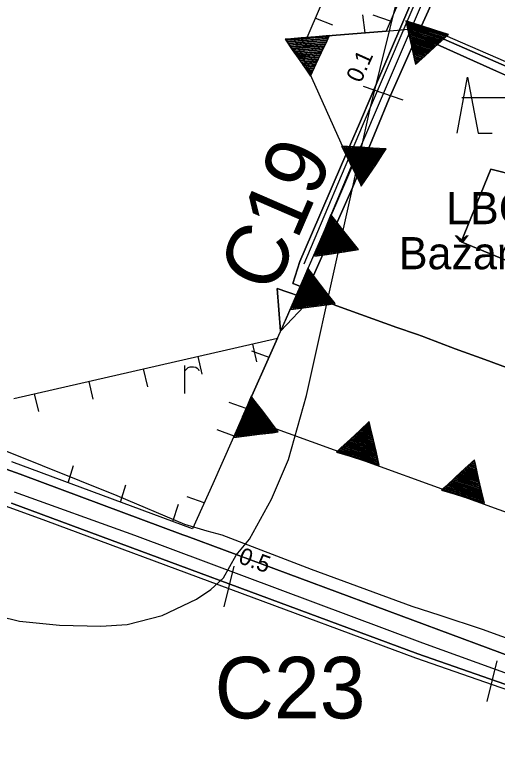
# Model space of a CAD drawing. Extents: x -645676 to -642474, y -1077513 to -1072613.
# Drawn here: x -643719.5 to -643546.9, y -1075297.8 to -1075036 of the extents above; entities that cross this region are included whole.
import ezdxf

# ---------------------------------------------------------------- set-up
doc = ezdxf.new("R2010")
doc.units = 0
for name, color, linetype in [('_elezni_n__tra_', 7, 'Continuous'), ('KULTURY_STAV', 7, 'Continuous'), ('KULTURY_ZNACKY', 7, 'Continuous'), ('Lok_ln__biocentrum___st_vaj_c_', 7, 'Continuous'), ('NERESENE_POZEMKY', 7, 'Continuous'), ('Obvod_KP_', 7, 'Continuous'), ('OBVOD_PU', 7, 'Continuous'), ('P__kop___st_vaj_c_', 7, 'Continuous'), ('PC_NAVRH', 7, 'Continuous'), ('PC_POPIS_NAVRH', 7, 'Continuous'), ('PC_POPIS_STAV', 7, 'Continuous'), ('PC_STAN_NAVRH', 7, 'Continuous'), ('PC_STAN_STAV', 7, 'Continuous'), ('PC_STAV', 7, 'Continuous'), ('SDELOVACI', 7, 'Continuous'), ('USES_BC_STAV', 7, 'Continuous'), ('USES_BK_NAVRH', 7, 'Continuous'), ('VRSTEVNICE', 7, 'Continuous')]:
    doc.layers.add(name, color=color, linetype=linetype)

# ---------------------------------------------------------------- blocks, each defined once
blk = doc.blocks.new('$943')
blk.add_line((0, 1.5), (0, -1.5))
blk = doc.blocks.new('$945')
for points in [[(0, 0), (-2.8, 1.25), (-2.8, -1.25), (0, 0)], [(-2.8, 1.25), (0, 0), (-2.8, -1.25), (-2.8, 1.25)]]:
    blk.add_lwpolyline(points)
blk = doc.blocks.new('$944')
blk.add_line((0, 1.5), (0, -1.5))
blk = doc.blocks.new('8$0300')
for p, q in [((-7.5, 0), (-1.5, 0)), ((1.5, 0), (7.5, 0))]:
    blk.add_line(p, q)
blk = doc.blocks.new('3$0800')
blk.add_lwpolyline([(-0.75, 0), (0, 4), (0.75, 0), (1.75, 0)])
blk = doc.blocks.new('$479')
for points in [[(0, 0), (0, 1.27), (0, 2)], [(0, 1.6), (0.1, 1.73), (0.23, 1.84), (0.37, 1.89), (0.6, 1.9), (0.77, 1.87), (0.87, 1.8), (0.96, 1.7), (1, 1.6)]]:
    blk.add_lwpolyline(points)
blk = doc.blocks.new('$1193')
for points in [[(2, 0), (0.73, 0), (-0.54, 0), (-1.81, 0), (-2, 0), (-1.43, -1), (-0.85, -2), (-0.27, -3), (0, -3.46), (0.57, -2.46), (1.15, -1.46), (1.73, -0.46), (2, 0)], [(-1.92, -0.04), (-0.65, -0.04), (0.62, -0.04), (1.89, -0.04), (1.92, -0.04), (1.84, -0.12), (0.57, -0.12), (-0.7, -0.12), (-1.84, -0.12), (-1.84, -0.2), (-0.57, -0.2), (0.7, -0.2), (1.84, -0.2), (1.76, -0.28), (0.49, -0.28), (-0.78, -0.28), (-1.76, -0.28), (-1.76, -0.36), (-0.49, -0.36), (0.78, -0.36), (1.76, -0.36), (1.68, -0.44), (0.41, -0.44), (-0.86, -0.44), (-1.68, -0.44), (-1.68, -0.52), (-0.41, -0.52), (0.86, -0.52), (1.68, -0.52), (1.6, -0.6), (0.33, -0.6), (-0.94, -0.6), (-1.6, -0.6), (-1.52, -0.68), (-0.25, -0.68), (1.02, -0.68), (1.52, -0.68), (1.52, -0.76), (0.25, -0.76), (-1.02, -0.76), (-1.52, -0.76), (-1.44, -0.84), (-0.17, -0.84), (1.1, -0.84), (1.44, -0.84), (1.44, -0.92), (0.17, -0.92), (-1.1, -0.92), (-1.44, -0.92), (-1.36, -1), (-0.09, -1), (1.18, -1), (1.36, -1), (1.36, -1.08), (0.09, -1.08), (-1.18, -1.08), (-1.36, -1.08), (-1.28, -1.16), (-0.01, -1.16), (1.26, -1.16), (1.28, -1.16), (1.2, -1.24), (-0.07, -1.24), (-1.2, -1.24), (-1.2, -1.32), (0.07, -1.32), (1.2, -1.32), (1.12, -1.4), (-0.15, -1.4), (-1.12, -1.4), (-1.12, -1.48), (0.15, -1.48), (1.12, -1.48), (1.04, -1.56), (-0.23, -1.56), (-1.04, -1.56), (-0.96, -1.64), (0.31, -1.64), (1.04, -1.64), (0.96, -1.72), (-0.31, -1.72), (-0.96, -1.72), (-0.88, -1.8), (0.39, -1.8), (0.88, -1.8), (0.88, -1.88), (-0.39, -1.88), (-0.88, -1.88), (-0.8, -1.96), (0.47, -1.96), (0.8, -1.96), (0.8, -2.04), (-0.47, -2.04), (-0.8, -2.04), (-0.72, -2.12), (0.55, -2.12), (0.72, -2.12), (0.64, -2.2), (-0.63, -2.2), (-0.64, -2.2), (-0.64, -2.28), (0.63, -2.28), (0.64, -2.28), (0.56, -2.36), (-0.64, -2.36), (-0.56, -2.44), (0.56, -2.44), (0.48, -2.52), (-0.48, -2.52), (-0.48, -2.6), (0.48, -2.6), (0.4, -2.68), (-0.4, -2.68), (-0.32, -2.76), (0.4, -2.76), (0.32, -2.84), (-0.32, -2.84), (-0.24, -2.92), (0.24, -2.92), (0.24, -3), (-0.24, -3), (-0.16, -3.08), (0.16, -3.08), (0.16, -3.16), (-0.16, -3.16), (-0.08, -3.24), (0.08, -3.24), (0.08, -3.32), (0, -3.32), (0, -3.4)]]:
    blk.add_lwpolyline(points)
blk = doc.blocks.new('2$1030')
blk.add_line((0, 0), (0, -0.5))

msp = doc.modelspace()

# ---------------------------------------------------------------- linework, layer by layer
at = {"layer": '_elezni_n__tra_'}
msp.add_lwpolyline([(-643719.69, -1075206.5), (-643676.68, -1075221.97), (-643573.6, -1075260.53), (-643522.3, -1075279.08), (-643429.01, -1075311.31)], dxfattribs=at)
at = {"layer": 'KULTURY_STAV'}
for points in [[(-643546.39, -1074976.36), (-643517.29, -1075011.03), (-643481.44, -1075057.16), (-643466.38, -1075082.52), (-643468.64, -1075087.39), (-643538.17, -1075056.97), (-643574.53, -1075041.03), (-643562.74, -1075014.92), (-643556.97, -1075002.06), (-643546.39, -1074976.36)], [(-643562.74, -1075014.92), (-643574.53, -1075041.03), (-643575.6, -1075043.46), (-643585.53, -1075066.02), (-643598.79, -1075098.13), (-643613.15, -1075130.31), (-643614.09, -1075132.49), (-643615.3, -1075135.81), (-643614.75, -1075134.3), (-643617.31, -1075133.2), (-643619.97, -1075132.07), (-643620.05, -1075132.03), (-643617.55, -1075124.24), (-643613.33, -1075114.51), (-643602.58, -1075089.7), (-643596.16, -1075074.91), (-643583.65, -1075045.64), (-643582.48, -1075042.91), (-643572.34, -1075019.19)], [(-643572.34, -1075019.19), (-643582.48, -1075042.91), (-643583.65, -1075045.64), (-643596.16, -1075074.91), (-643602.58, -1075089.7), (-643613.33, -1075114.51), (-643617.55, -1075124.24), (-643620.05, -1075132.03), (-643619.97, -1075132.07), (-643617.31, -1075133.2), (-643614.75, -1075134.3), (-643615.3, -1075135.81), (-643604.27, -1075140.06), (-643582.89, -1075147.83), (-643575.74, -1075150.21), (-643573.79, -1075150.89), (-643573.23, -1075151.11), (-643561.96, -1075155.43), (-643551.32, -1075159.24), (-643509.71, -1075174.55)], [(-643574.53, -1075041.03), (-643538.17, -1075056.97), (-643468.64, -1075087.39), (-643469.81, -1075089.86), (-643520.92, -1075067.85), (-643536.4, -1075061.02), (-643547.18, -1075056.15), (-643575.6, -1075043.46), (-643574.53, -1075041.03)], [(-643509.71, -1075174.55), (-643551.32, -1075159.24), (-643561.96, -1075155.43), (-643573.23, -1075151.11), (-643573.79, -1075150.89), (-643575.74, -1075150.21), (-643582.89, -1075147.83), (-643604.27, -1075140.06), (-643615.3, -1075135.81), (-643614.09, -1075132.49), (-643613.15, -1075130.31), (-643598.79, -1075098.13), (-643585.53, -1075066.02), (-643575.6, -1075043.46)], [(-643575.6, -1075043.46), (-643547.18, -1075056.15), (-643536.4, -1075061.02)], [(-643520.92, -1075067.85), (-643469.81, -1075089.86), (-643487.57, -1075133.34), (-643493.33, -1075147.35), (-643507.39, -1075138.44), (-643526.84, -1075130.75), (-643559.77, -1075117.14), (-643549.25, -1075091.16), (-643530.35, -1075096.03), (-643520.92, -1075067.85)], [(-643530.35, -1075096.03), (-643549.25, -1075091.16), (-643559.77, -1075117.14), (-643526.84, -1075130.75)], [(-643737.72, -1075193.07), (-643717.58, -1075200.24), (-643659.37, -1075221.84), (-643659.38, -1075221.86), (-643657.95, -1075222.36), (-643536.7, -1075267.35), (-643449.86, -1075296.83), (-643452.16, -1075302.98), (-643453.56, -1075306.86), (-643575.29, -1075264.44), (-643720.69, -1075210.59)], [(-643368.43, -1075240.98), (-643386.32, -1075233.34), (-643421.39, -1075217.77), (-643424.82, -1075227.98), (-643440.64, -1075272.22), (-643449.86, -1075296.83), (-643536.7, -1075267.35), (-643657.95, -1075222.36), (-643659.38, -1075221.86), (-643659.37, -1075221.84), (-643717.58, -1075200.24), (-643737.72, -1075193.07)], [(-643720.69, -1075210.59), (-643575.29, -1075264.44), (-643453.56, -1075306.86), (-643452.16, -1075302.98), (-643455.39, -1075311.95), (-643456.38, -1075314.82), (-643466.87, -1075342.71), (-643475.27, -1075365.52), (-643445.59, -1075403.32), (-643437.59, -1075413.3), (-643423.39, -1075434.15), (-643405.02, -1075461.99)]]:
    msp.add_lwpolyline(points, dxfattribs=at)
at = {"layer": 'NERESENE_POZEMKY'}
msp.add_lwpolyline([(-643509.71, -1075174.55), (-643551.32, -1075159.24), (-643561.96, -1075155.43), (-643573.23, -1075151.11), (-643573.79, -1075150.89), (-643575.74, -1075150.21), (-643582.89, -1075147.83), (-643604.27, -1075140.06), (-643615.3, -1075135.81), (-643614.09, -1075132.49), (-643613.15, -1075130.31), (-643598.79, -1075098.13), (-643585.53, -1075066.02), (-643575.6, -1075043.46), (-643574.53, -1075041.03), (-643562.74, -1075014.92)], dxfattribs=at)
at = {"layer": 'Obvod_KP_'}
msp.add_lwpolyline([(-643509.71, -1075174.55), (-643551.32, -1075159.24), (-643561.96, -1075155.43), (-643573.23, -1075151.11), (-643573.79, -1075150.89), (-643575.74, -1075150.21), (-643582.89, -1075147.83), (-643604.27, -1075140.06), (-643615.3, -1075135.81), (-643614.09, -1075132.49), (-643613.15, -1075130.31), (-643598.79, -1075098.13), (-643585.53, -1075066.02), (-643575.6, -1075043.46), (-643574.53, -1075041.03), (-643562.74, -1075014.92)], dxfattribs=at)
at = {"layer": 'OBVOD_PU'}
msp.add_lwpolyline([(-643509.71, -1075174.55), (-643551.32, -1075159.24), (-643561.96, -1075155.43), (-643573.23, -1075151.11), (-643573.79, -1075150.89), (-643575.74, -1075150.21), (-643582.89, -1075147.83), (-643604.27, -1075140.06), (-643615.3, -1075135.81), (-643614.09, -1075132.49), (-643613.15, -1075130.31), (-643598.79, -1075098.13), (-643585.53, -1075066.02), (-643575.6, -1075043.46), (-643574.53, -1075041.03), (-643562.74, -1075014.92)], dxfattribs=at)
at = {"layer": 'P__kop___st_vaj_c_'}
msp.add_lwpolyline([(-643616.01, -1075125.08), (-643595.06, -1075075.72), (-643571.29, -1075019.94), (-643560.26, -1074994.78)], dxfattribs=at)
at = {"layer": 'PC_NAVRH'}
msp.add_lwpolyline([(-644115.89, -1075090.04), (-644061.03, -1075087.73), (-643984.83, -1075115.73), (-643862.1, -1075160.96), (-643708.49, -1075216.75), (-643576.12, -1075265.87), (-643454.04, -1075308.27)], dxfattribs=at)
at = {"layer": 'PC_STAV'}
msp.add_lwpolyline([(-643547.63, -1074972.51), (-643555.63, -1074989.35), (-643604.37, -1075103.28), (-643624.41, -1075149.11)], dxfattribs=at)
at = {"layer": 'SDELOVACI'}
msp.add_lwpolyline([(-643370.78, -1075316.8), (-643412.38, -1075303.82), (-643437.06, -1075295.73), (-643437.37, -1075295.52), (-643465.8, -1075287.04), (-643503.79, -1075273.28), (-643552.17, -1075255.78), (-643567.35, -1075250.69), (-643577.32, -1075247.48), (-643613.36, -1075234.33), (-643645.32, -1075222.06), (-643650.66, -1075220.63), (-643658.71, -1075218.16), (-643682.9, -1075207.99), (-643722.89, -1075191.92)], dxfattribs=at)
at = {"layer": 'USES_BC_STAV'}
msp.add_lwpolyline([(-643637.99, -1075179.73), (-643625.49, -1075151.66), (-643621.78, -1075143.34), (-643617.72, -1075134.02), (-643609.41, -1075114.88), (-643599.07, -1075090.12), (-643619.57, -1075044.53), (-643614.85, -1075044.14), (-643586.65, -1075041.85), (-643571.97, -1075040.65), (-643534.91, -1075056.63), (-643464.99, -1075087.04), (-643466.1, -1075089.54), (-643470.62, -1075099.64), (-643472.76, -1075104.94), (-643476.61, -1075113.96), (-643484.03, -1075132.87), (-643489.92, -1075146.84), (-643498.76, -1075167.93), (-643502.24, -1075175.78), (-643521.56, -1075221.89)], close=True, dxfattribs=at)
at = {"layer": 'USES_BK_NAVRH'}
for points in [[(-643140.05, -1074334.77), (-643371.48, -1074723.77), (-643386.93, -1074710.69), (-643471.56, -1074774.24), (-643586.65, -1075041.85), (-643614.85, -1075044.14), (-643491.9, -1074758.24), (-643387.13, -1074679.58), (-643365.02, -1074664.02), (-643154.25, -1074308.76)], [(-643719.82, -1075173.18), (-643625.49, -1075151.66), (-643637.99, -1075179.73), (-643648.64, -1075203.64), (-643655.91, -1075219.78), (-643720.5, -1075195.81)]]:
    msp.add_lwpolyline(points, dxfattribs=at)
at = {"layer": 'VRSTEVNICE'}
for points in [[(-643592.44, -1075070.19), (-643566.8, -1074966.79)], [(-643732.01, -1075249.35), (-643717.77, -1075252.77), (-643703.53, -1075254.2), (-643688.72, -1075254.48), (-643679.32, -1075253.91), (-643666.78, -1075250.78), (-643654.54, -1075244.94), (-643649.41, -1075241.38), (-643644.85, -1075237.25), (-643640.29, -1075229.13), (-643635.59, -1075223.43), (-643627.62, -1075209.19), (-643621.64, -1075194.95), (-643615.09, -1075172.16), (-643592.44, -1075070.19)]]:
    msp.add_lwpolyline(points, dxfattribs=at)

# ---------------------------------------------------------------- block references
at = {"layer": 'KULTURY_ZNACKY', "xscale": 5, "yscale": 5}
for name, p in [('3$0800', (-643557.52, -1075078.32)), ('8$0300', (-643522.1, -1075065.66)), ('$479', (-643658.61, -1075171.34))]:
    msp.add_blockref(name, p, dxfattribs=at)
at = {"layer": 'PC_STAN_NAVRH', "xscale": 5, "yscale": 5, "rotation": -13.845487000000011}
for p in [(-643642.92, -1075240.33), (-643548.82, -1075274.18)]:
    msp.add_blockref('$944', p, dxfattribs=at)
at = {"layer": 'PC_STAN_STAV', "xscale": 5}
for name, p, yscale, rotation in [('$943', (-643587.63, -1075064.15), 4.999999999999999, -108.855939), ('$945', (-643624.41, -1075149.11), 5, -109.322327)]:
    msp.add_blockref(name, p, dxfattribs=dict(at, yscale=yscale, rotation=rotation))
at = {"layer": 'USES_BC_STAV', "yscale": 4}
for p, xscale, rotation in [((-643571.97, -1075040.65), 4, -17.449277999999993), ((-643614.85, -1075044.14), 4, 4.738512), ((-643599.07, -1075090.12), 4, 116.200739), ((-643609.41, -1075114.88), 4, 68.509345), ((-643617.72, -1075134.02), 3.9999999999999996, 67.692179), ((-643637.99, -1075179.73), 3.9999999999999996, 67.141787), ((-643596.78, -1075194.65), 4, 162.88451799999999), ((-643559.17, -1075208.27), 4, 162.88451799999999)]:
    msp.add_blockref('$1193', p, dxfattribs=dict(at, xscale=xscale, rotation=rotation))
at = {"layer": 'USES_BK_NAVRH'}
for p, xscale, yscale, rotation in [((-643594.12, -1075042.45), 12.999999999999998, 13.000000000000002, -172.11989900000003), ((-643585.14, -1075038.35), 13, 13.000000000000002, -108.96340500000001), ((-643611.89, -1075037.25), 13, 13, 67.895018), ((-643634.52, -1075153.72), 13, 13, 13.075831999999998), ((-643628.54, -1075158.51), 13.000000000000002, 12.999999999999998, -109.716636), ((-643654.01, -1075158.17), 13, 13, 13.075831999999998), ((-643673.51, -1075162.62), 13, 13, 13.075831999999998), ((-643693.01, -1075167.07), 13, 13, 13.075831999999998), ((-643712.51, -1075171.52), 13, 13, 13.075831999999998), ((-643636.68, -1075176.78), 13.000000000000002, 12.999999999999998, -109.716636), ((-643641.04, -1075186.58), 13.000000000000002, 13, -109.716775), ((-643700.44, -1075203.26), 13, 13, 162.43319599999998), ((-643681.69, -1075210.21), 13, 13, 162.43319599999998), ((-643651.72, -1075210.48), 13, 13.000000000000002, -109.95488900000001), ((-643662.94, -1075217.17), 13, 13, 162.43319599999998)]:
    msp.add_blockref('2$1030', p, dxfattribs=dict(at, xscale=xscale, yscale=yscale, rotation=rotation))

# ---------------------------------------------------------------- texts
at = {"layer": 'Lok_ln__biocentrum___st_vaj_c_'}
for s, p in [('LBC 3', (-643565.2, -1075110.89)), ('Bažantnice', (-643582.1, -1075126.99))]:
    msp.add_text(s, height=11.5, dxfattribs=at).set_placement(p)
at = {"layer": 'PC_POPIS_NAVRH'}
msp.add_text('C23', height=22, dxfattribs=at).set_placement((-643648.02, -1075287.5))
at = {"layer": 'PC_POPIS_STAV'}
msp.add_text('C19', height=22, rotation=66.578, dxfattribs=at).set_placement((-643626.99, -1075136.39))
at = {"layer": 'PC_STAN_NAVRH'}
msp.add_text('0.5', height=6, rotation=340.222, dxfattribs=at).set_placement((-643639.88, -1075231.86))
at = {"layer": 'PC_STAN_STAV'}
msp.add_text('0.1', height=6, rotation=65.718, dxfattribs=at).set_placement((-643595.74, -1075060.68))

doc.saveas('drawing.dxf')
